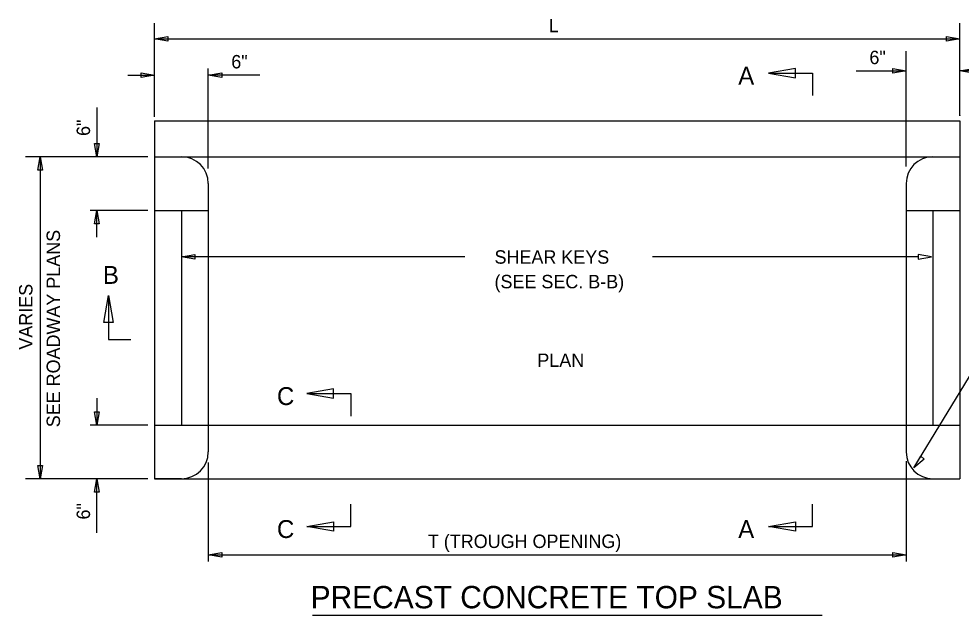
# Model space of a CAD drawing. Extents: x 12.4 to 21.1, y 6 to 16.1.
# Drawn here: x 12.444 to 16.657, y 13.472 to 16.138 of the extents above; entities that cross this region are included whole.
import ezdxf

# ---------------------------------------------------------------- set-up
doc = ezdxf.new("R2010")
doc.units = 0
for name, color, linetype in [('V7_LEVEL_1', 7, 'Continuous'), ('V7_LEVEL_10', 7, 'Continuous'), ('V7_LEVEL_12', 7, 'Continuous'), ('V7_LEVEL_44', 7, 'Continuous')]:
    doc.layers.add(name, color=color, linetype=linetype)

msp = doc.modelspace()

# ---------------------------------------------------------------- linework, layer by layer
at = {"layer": 'V7_LEVEL_1'}
for p, q in [((13.0508, 15.6816), (13.0508, 14.0816)), ((13.0508, 15.6816), (16.6508, 15.6816)), ((16.6508, 15.6816), (16.6508, 14.0816)), ((13.0508, 15.5216), (16.6508, 15.5216)), ((13.0508, 15.5216), (13.1708, 15.5216)), ((16.5308, 15.5216), (16.6508, 15.5216)), ((13.2908, 15.4016), (13.2908, 14.2016)), ((16.4108, 15.4016), (16.4108, 14.2016)), ((13.0508, 15.2816), (13.2908, 15.2816)), ((13.1708, 15.2816), (13.1708, 14.3216)), ((16.4108, 15.2816), (16.6508, 15.2816)), ((16.5308, 15.2816), (16.5308, 14.3216)), ((13.0508, 14.3216), (16.6508, 14.3216)), ((13.0508, 14.0816), (16.6508, 14.0816)), ((13.1708, 14.0816), (13.0508, 14.0816)), ((16.5308, 14.0816), (16.6508, 14.0816))]:
    msp.add_line(p, q, dxfattribs=at)
for centre, start, end in [((13.1708, 15.4016), 0, 90), ((16.5308, 15.4016), 90, 180), ((13.1708, 14.2016), 270, 0), ((16.5308, 14.2016), 180, 270)]:
    msp.add_arc(centre, 0.12, start, end, dxfattribs=at)
at = {"layer": 'V7_LEVEL_10'}
for p, q in [((13.0508, 15.7054), (13.0508, 16.1194)), ((16.6508, 15.7047), (16.6508, 16.1194)), ((13.0508, 16.0485), (16.6508, 16.0485)), ((16.4108, 15.4781), (16.4108, 15.9933)), ((12.9308, 15.8866), (13.0508, 15.8866)), ((13.2908, 15.4688), (13.2908, 15.9166)), ((13.5207, 15.8866), (13.2908, 15.8866)), ((15.7955, 15.8954), (15.9923, 15.8954)), ((15.9923, 15.8954), (15.9923, 15.7951)), ((16.1868, 15.906), (16.4108, 15.906)), ((16.7708, 15.906), (16.6508, 15.906)), ((12.7926, 15.7415), (12.7926, 15.5216)), ((13.0508, 15.6999), (13.0508, 15.7047)), ((16.6508, 15.7064), (16.6508, 15.7047)), ((13.0208, 15.5216), (12.4741, 15.5216)), ((12.5389, 15.5216), (12.5389, 14.0816)), ((13.0208, 15.5216), (12.7626, 15.5216)), ((13.0208, 15.2816), (12.7626, 15.2816)), ((13.0208, 15.2816), (12.7626, 15.2816)), ((12.7926, 15.1616), (12.7926, 15.2816)), ((14.4372, 15.0741), (13.1708, 15.0741)), ((16.467, 15.0741), (15.2768, 15.0741)), ((12.8443, 14.901), (12.8443, 14.7042)), ((12.8443, 14.7042), (12.9446, 14.7042)), ((13.7309, 14.4623), (13.9278, 14.4623)), ((13.9278, 14.4623), (13.9278, 14.3621)), ((12.7926, 14.4416), (12.7926, 14.3216)), ((13.0208, 14.3216), (12.7626, 14.3216)), ((16.4108, 14.1608), (16.4108, 13.712)), ((13.2908, 14.1546), (13.2908, 13.712)), ((13.0208, 14.0816), (12.4741, 14.0816)), ((13.0208, 14.0816), (12.7626, 14.0816)), ((12.7926, 13.8394), (12.7926, 14.0816)), ((13.9278, 13.8678), (13.9278, 13.9681)), ((15.9923, 13.8678), (15.9923, 13.9681)), ((13.7309, 13.8678), (13.9278, 13.8678)), ((15.7955, 13.8678), (15.9923, 13.8678)), ((13.2908, 13.742), (16.4108, 13.742))]:
    msp.add_line(p, q, dxfattribs=at)
for points in [[(13.1108, 16.038), (13.0508, 16.0485), (13.1108, 16.059)], [(16.5908, 16.059), (16.6508, 16.0485), (16.5908, 16.038)], [(12.9908, 15.8971), (13.0508, 15.8866), (12.9908, 15.8761)], [(13.3508, 15.8761), (13.2908, 15.8866), (13.3508, 15.8971)], [(15.9155, 15.9164), (15.7955, 15.8954), (15.9155, 15.8744)], [(16.3508, 15.9165), (16.4108, 15.906), (16.3508, 15.8955)], [(16.7108, 15.8955), (16.6508, 15.906), (16.7108, 15.9165)], [(12.8031, 15.5816), (12.7926, 15.5216), (12.7821, 15.5816)], [(12.5292, 15.4616), (12.5397, 15.5216), (12.5502, 15.4616)], [(12.7821, 15.2216), (12.7926, 15.2816), (12.8031, 15.2216)], [(13.2308, 15.0636), (13.1708, 15.0741), (13.2308, 15.0846)], [(16.4643, 15.0636), (16.5243, 15.0741), (16.4643, 15.0846)], [(12.8233, 14.781), (12.8443, 14.901), (12.8653, 14.781)], [(13.8509, 14.4833), (13.7309, 14.4623), (13.8509, 14.4413)], [(12.8031, 14.3816), (12.7926, 14.3216), (12.7821, 14.3816)], [(16.4918, 14.1688), (16.4445, 14.1304), (16.476, 14.1825)], [(12.5502, 14.1416), (12.5397, 14.0816), (12.5292, 14.1416)], [(12.7821, 14.0216), (12.7926, 14.0816), (12.8031, 14.0216)], [(13.8509, 13.8468), (13.7309, 13.8678), (13.8509, 13.8888)], [(15.9155, 13.8468), (15.7955, 13.8678), (15.9155, 13.8888)], [(13.3508, 13.7315), (13.2908, 13.742), (13.3508, 13.7525)], [(16.3508, 13.7525), (16.4108, 13.742), (16.3508, 13.7315)]]:
    msp.add_lwpolyline(points, close=True, dxfattribs=at)
msp.add_lwpolyline([(16.4445, 14.1304), (16.7101, 14.5657), (16.8177, 14.5657)], dxfattribs=at)
at = {"layer": 'V7_LEVEL_44'}
msp.add_line((13.7566, 13.4716), (16.0356, 13.4716), dxfattribs=at)

# ---------------------------------------------------------------- texts
at = {"layer": 'V7_LEVEL_12'}
for s, height, p in [('L', 0.06, (14.8131, 16.0784)), ('6"', 0.06, (13.3938, 15.9167)), ('6"', 0.06, (16.2466, 15.9359)), ('A', 0.08, (15.6602, 15.8442)), ('SHEAR KEYS ', 0.06, (14.5706, 15.0433)), ('B', 0.08, (12.8199, 14.9532)), ('(SEE SEC. B-B)', 0.06, (14.5706, 14.9333)), ('PLAN', 0.06, (14.762, 14.5815)), ('C', 0.08, (13.598, 14.4112)), ('C', 0.08, (13.598, 13.8167)), ('A', 0.08, (15.6602, 13.8167)), ('T (TROUGH OPENING)', 0.06, (14.2726, 13.7719)), ('PRECAST CONCRETE TOP SLAB', 0.1, (13.7486, 13.5022))]:
    msp.add_text(s, height=height, dxfattribs=at).set_placement(p)
for s, p in [('6"', (12.7623, 15.6147)), ('SEE ROADWAY PLANS', (12.6281, 14.3119)), ('VARIES', (12.5049, 14.6589)), ('6"', (12.7623, 13.8994))]:
    msp.add_text(s, height=0.06, rotation=90, dxfattribs=at).set_placement(p)

doc.saveas('drawing.dxf')
